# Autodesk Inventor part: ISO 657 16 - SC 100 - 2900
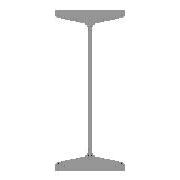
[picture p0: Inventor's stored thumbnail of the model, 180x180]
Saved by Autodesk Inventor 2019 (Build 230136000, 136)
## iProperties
_CCFamilyMember: 1
_CCFamilyDisplayName: ISO 657/16 - 1980 - Poutres en acier laminées à chaud - Partie 16: profilés en H (série métrique) - Cotes et propriétés de section
_FrameMemberDoc: Frame Member File
_Version: 15.0.0
_GetPNFromCC: 1
Created: 2018-01
Part Number: ISO 657 16 - SC 100 - 2900
Material: Acier, doux
Description: Poutres en acier laminées à chaud - Partie 16: profilés en H (série métrique) - Cotes et propriétés de section
Document SubType Name: Modeling
Standard: ISO
Designer: Fabian Perrée
Standard Revision: First edition 1980-02-15
Standards Organization: ISO
Language: fr-FR
Size Designation: SC 100
Categories: <MemberInstance><Categories><Category DisplayName="Profilés" InternalName="089c4875-fa83-4c05-b084-43b9cc11f5ed" Mnemonic="GRDR"><CategoryParameter DisplayName=
Stock Number: SC 100
Density: 7.85 g/cm^3
Appearance: Semi-poli
Mass: 57968.8 g
Surface Area: 15748.4 cm^2
Volume: 7384.56 cm^3
IsCustomPart: 1
G_W: 100,000 mm
G_H: 100,000 mm
+7C75FE93-44B4-4967-A4EC-28715C0C1D86+DETAILDECOUPE1: Angle de coupe 90,00 deg
G_L: 2900,000 mm
Author: Fabian Perrée
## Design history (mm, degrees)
node "Plan de départ"
node "Plan de fin"
sketch "Esquisse"
  geometry: L1 (-3, 0)-(-3, -26.266); L2 (-13.33, -38.149)-(-44.835, -42.577); L3 (-50, -48.518)-(-50, -50); L4 (-50, -50)-(0, -50); L5 (-26.5, -50)-(-26.5, -40); L6 (-61.333, 0)-(81.777, 0); L7 (0, 0)-(0, -50); L8 (0, -60)-(0, 80); L9 (3, 0)-(3, -26.266); L10 (13.33, -38.149)-(44.835, -42.577); L11 (50, -48.518)-(50, -50); L12 (50, -50)-(0, -50); L13 (-3, 0)-(0, 0); L14 (-3, 0)-(-3, 26.266); L15 (-13.33, 38.149)-(-44.835, 42.577); L16 (-50, 48.518)-(-50, 50); L17 (-50, 50)-(0, 50); L18 (50, 48.518)-(50, 50); L19 (13.33, 38.149)-(44.835, 42.577); L20 (3, 0)-(3, 26.266); L21 (50, 50)-(0, 50); L22 (0, 108)-(0, -88) reference; L23 (-89.955, 0)-(110.399, 0) reference; A1 r 6 centre (-44, 48.518) between (-50, 48.518) and (-44.835, 42.577); A2 r 6 centre (44, 48.518) between (44.835, 42.577) and (50, 48.518); A3 r 6 centre (44, -48.518) between (50, -48.518) and (44.835, -42.577); A4 r 6 centre (-44, -48.518) between (-44.835, -42.577) and (-50, -48.518); A5 r 12 centre (-15, 26.266) between (-3, 26.266) and (-13.33, 38.149); A6 r 12 centre (15, 26.266) between (13.33, 38.149) and (3, 26.266); A7 r 12 centre (15, -26.266) between (3, -26.266) and (13.33, -38.149); A8 r 12 centre (-15, -26.266) between (-13.33, -38.149) and (-3, -26.266); 14 further points
  constraints: 42 end point, 24 point on line, 17 symmetric about line, 16 point on circle, 16 tangent, 8 centre point, 6 equal radius, 4 collinear, 2 perpendicular, 12 other
  dimensions: "d1" = 10 vertical distance of L3.end L5.end (= G_T1); "d2" = 23.5 distance between parallel lines of L5 L3 (= -0.25 x G_T + 0.25 x G_W); "d3" = 3 distance between parallel lines of L1 L7 (= 0.5 x G_T); "d4" = 50 distance between parallel lines of L7 L3 (= 0.5 x G_W); "d9" = 50 distance from line of L1.start L4 (= 0.5 x G_H); "d14" = 98 deg angle of L2 L1 (= G_NG); "d15" = 6 radius of A1 (= G_ER); "d16" = 12 radius of A5 (= G_IR)
extrude "Corps" new body sketch "Esquisse" stored distance "d5" = 2900 (= G_L); taper "d6" = 0 deg
node "Driven Length"
  sketch "Sketch3"
    geometry: L1 (0, 0)-(10, 0) reference
    constraints: 2 end point, 1 horizontal
  workplane "Work Plane3"
  sketch "Sketch4"
    geometry: L1 (-2, 0)-(12, 0) reference; L2 (-2, 2900)-(12, 2900) reference
    dimensions: "d20" = 2900 distance between parallel lines of L1 L2 (derived)
node "Plan de construction4"
feature "Scission1"
body "Solid1"
other parameters: "G_W" = 100 (= G_H) [user parameter; used in 2 equation terms], "G_H" = 100 [user parameter; used in 2 equation terms], "G_T" = 6 [user parameter; used in 2 equation terms], "G_T1" = 10 [user parameter; used in 1 equation term], "G_L" = 2900 (= d20) [user parameter; used in 1 equation term], "G_ER" = 6 [user parameter; used in 1 equation term], "G_IR" = 12 [user parameter; used in 1 equation term], "G_NG" = 98 deg [user parameter; used in 1 equation term], "G_OFFSET_START" = 0 [user parameter; used in 1 equation term], "d17" = 0 (computed from G_OFFSET_START), "d19" = 90 deg
